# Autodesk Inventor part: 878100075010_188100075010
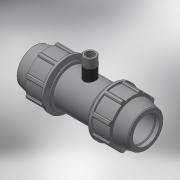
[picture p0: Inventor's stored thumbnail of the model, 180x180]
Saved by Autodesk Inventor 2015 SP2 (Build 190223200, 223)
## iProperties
Created: 2017-02
Part Number: 878100075010_188100075010
Material: Generic
Description: PLASSON COUPLER WITH RISER 75-1"
Document SubType Name: Modeling
Designer: KIM
Mass: 1772.99 g
Surface Area: 2354.31 cm^2
Volume: 1772.99 cm^3
Density: 1 g/cm^3
Appearance: Default
Author: KIM
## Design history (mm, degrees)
derived "87810.ipt"
feature "Solid1::87810.ipt"
feature "Solid2::87810.ipt"
tag "TaggingFeature1"
body "Solid1"
other parameters: "d2" = 75, "d4" = 13.5, "d5" = 38.88, "d7" = 132, "d11" = 5.4, "d13" = 120 deg, "d14" = 97.5, "d15" = 12 deg, "d16" = 114.84, "d18" = 3.75, "d19" = 35 deg, "d20" = 17.5 deg, "d21" = 122.76, "d23" = 0, "d25" = 360 deg, "d27" = 2.64, "d33" = 1.5, "d42" = 58.32, "d43" = 3.96, "d46" = 2.25, "d68" = 5.4, "d72" = 105, "d73" = 33.249, "d76" = 23.2743, "d77" = 24, "d80" = 0.99747, "d91" = 99, "d93" = 137, "d95" = 67.5, "d99" = 324, "d101" = 0, "d103" = 0, "d105" = 0, "d106" = 33.91398, "d107" = 6.48, "d108" = 0, "d_" = 75, "E_" = 132, "A_" = 105, "l_" = 137, "H_" = 324, "R_" = 33.249
